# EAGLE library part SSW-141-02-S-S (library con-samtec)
THROUGH-HOLE .025" SQ POST SOCKET Source: Samtec SSW.pdf
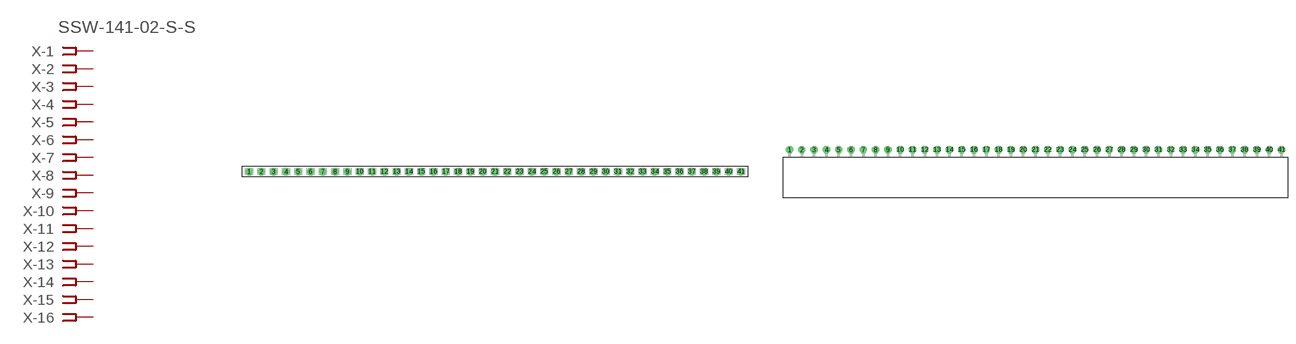
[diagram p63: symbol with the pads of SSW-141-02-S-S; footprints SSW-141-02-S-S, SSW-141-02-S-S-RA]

Designator prefix X; gates -1=FPINV -2=FPIN -3=FPIN -4=FPIN -5=FPIN -6=FPIN -7=FPIN -8=FPIN -9=FPIN -10=FPIN -11=FPIN -12=FPIN -13=FPIN -14=FPIN -15=FPIN -16=FPIN -17=FPIN -18=FPIN -19=FPIN -20=FPIN -21=FPIN -22=FPIN -23=FPIN -24=FPIN -25=FPIN -26=FPIN -27=FPIN -28=FPIN -29=FPIN -30=FPIN -31=FPIN -32=FPIN -33=FPIN -34=FPIN -35=FPIN -36=FPIN -37=FPIN -38=FPIN -39=FPIN -40=FPIN -41=FPIN

## SSW-141-02-S-S (MPN: SSW-141-02-S-S; OC_FARNELL: unknown; OC_NEWARK: 11P9968)  [SSW-141-02-S-S]
1  -1:1  pas
2  -2:1  pas
3  -3:1  pas
4  -4:1  pas
5  -5:1  pas
6  -6:1  pas
7  -7:1  pas
8  -8:1  pas
9  -9:1  pas
10  -10:1  pas
11  -11:1  pas
12  -12:1  pas
13  -13:1  pas
14  -14:1  pas
15  -15:1  pas
16  -16:1  pas
17  -17:1  pas
18  -18:1  pas
19  -19:1  pas
20  -20:1  pas
21  -21:1  pas
22  -22:1  pas
23  -23:1  pas
24  -24:1  pas
25  -25:1  pas
26  -26:1  pas
27  -27:1  pas
28  -28:1  pas
29  -29:1  pas
30  -30:1  pas
31  -31:1  pas
32  -32:1  pas
33  -33:1  pas
34  -34:1  pas
35  -35:1  pas
36  -36:1  pas
37  -37:1  pas
38  -38:1  pas
39  -39:1  pas
40  -40:1  pas
41  -41:1  pas

## SSW-141-02-S-S-RA (OC_FARNELL: unknown; OC_NEWARK: unknown)  [SSW-141-02-S-S-RA]
Pads as for SSW-141-02-S-S

## Footprint SSW-141-02-S-S (pad centres in mm)
THROUGH-HOLE .025" SQ POST SOCKET Source: Samtec SSW.pdf
drill 1 pad 1.5 octagon: 1 -50.8,0; 2 -48.26,0; 3 -45.72,0; 4 -43.18,0; 5 -40.64,0; 6 -38.1,0; 7 -35.56,0; 8 -33.02,0; 9 -30.48,0; 10 -27.94,0; 11 -25.4,0; 12 -22.86,0; 13 -20.32,0; 14 -17.78,0; 15 -15.24,0; 16 -12.7,0; 17 -10.16,0; 18 -7.62,0; 19 -5.08,0; 20 -2.54,0; 21 0,0; 22 2.54,0; 23 5.08,0; 24 7.62,0; 25 10.16,0; 26 12.7,0; 27 15.24,0; 28 17.78,0; 29 20.32,0; 30 22.86,0; 31 25.4,0; 32 27.94,0; 33 30.48,0; 34 33.02,0; 35 35.56,0; 36 38.1,0; 37 40.64,0; 38 43.18,0; 39 45.72,0; 40 48.26,0; 41 50.8,0

## Footprint SSW-141-02-S-S-RA (pad centres in mm)
THROUGH-HOLE .025" SQ POST SOCKET Source: Samtec SSW.pdf
drill 1 pad 1.5 octagon: 1 -50.8,1.524; 2 -48.26,1.524; 3 -45.72,1.524; 4 -43.18,1.524; 5 -40.64,1.524; 6 -38.1,1.524; 7 -35.56,1.524; 8 -33.02,1.524; 9 -30.48,1.524; 10 -27.94,1.524; 11 -25.4,1.524; 12 -22.86,1.524; 13 -20.32,1.524; 14 -17.78,1.524; 15 -15.24,1.524; 16 -12.7,1.524; 17 -10.16,1.524; 18 -7.62,1.524; 19 -5.08,1.524; 20 -2.54,1.524; 21 0,1.524; 22 2.54,1.524; 23 5.08,1.524; 24 7.62,1.524; 25 10.16,1.524; 26 12.7,1.524; 27 15.24,1.524; 28 17.78,1.524; 29 20.32,1.524; 30 22.86,1.524; 31 25.4,1.524; 32 27.94,1.524; 33 30.48,1.524; 34 33.02,1.524; 35 35.56,1.524; 36 38.1,1.524; 37 40.64,1.524; 38 43.18,1.524; 39 45.72,1.524; 40 48.26,1.524; 41 50.8,1.524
